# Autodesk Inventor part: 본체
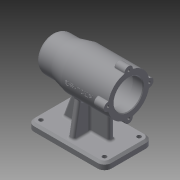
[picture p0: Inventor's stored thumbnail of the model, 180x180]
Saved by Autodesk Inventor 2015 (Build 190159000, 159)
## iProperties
Created: 2019-07
Part Number: 본체
Material: 일반
Document SubType Name: Modeling
Designer: now060
Density: 1 g/cm^3
Appearance: 기본값
Author: now060
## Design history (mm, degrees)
sketch "스케치1"
  geometry: L1 (-56, -35)-(56, -35); L2 (56, -35)-(56, 35); L3 (56, 35)-(-56, 35); L4 (-56, 35)-(-56, -35); L5 (-56, -35)-(56, 35); L6 (56, -35)-(-56, 35); 1 further point
  constraints: 12 end point, 2 midpoint, 2 parallel, 1 horizontal, 1 perpendicular
  dimensions: "d0" = 112 distance of L2.end L3.end; "d1" = 70 distance of L1.end L2.end
extrude "돌출1" new body sketch "스케치1" distance "d2" = 10; taper "d3" = 0 deg
sketch "스케치2"
  geometry: L1 (56, -35)-(56, 35) reference; L2 (-56, 35)-(-56, -35) reference; L3 (-36, 4)-(31, 4); L4 (31, 4)-(31, -4); L5 (31, -4)-(-36, -4); L6 (-36, -4)-(-36, 4); 1 further point
  constraints: 8 end point, 2 parallel, 1 horizontal, 1 perpendicular
  dimensions: "d4" = 25 distance between parallel lines of L1 L4; "d5" = 20 distance between parallel lines of L6 L2; "d6" = 4 distance from line of L3 point (0, 0); "d7" = 8 distance between parallel lines of L5 L3
extrude "돌출2" join sketch "스케치2" distance "d8" = 70; taper "d9" = 0 deg
sketch "스케치3"
  geometry: L1 (56, 35)-(-56, 35) reference; L2 (4, -28)-(-4, -28); L3 (-4, -28)-(-4, 28); L4 (-4, 28)-(4, 28); L5 (4, 28)-(4, -28); L6 (4, -28)-(-4, 28); L7 (-4, -28)-(4, 28); 1 further point
  constraints: 12 end point, 2 midpoint, 2 parallel, 1 horizontal, 1 perpendicular
  dimensions: "d10" = 8 distance between parallel lines of L5 L3; "d11" = 7 distance between parallel lines of L1 L4
extrude "돌출3" join sketch "스케치3" distance "d12" = 70; taper "d13" = 0 deg
feature "면 기울기1" dims angle "d14" = 10 deg
feature "면 기울기2" dims angle "d15" = 20 deg
sketch "스케치4"
  geometry: L1 (-56, 0)-(-56, 10) reference; L2 (-56, 10)-(-31, 10) reference; L3 (-31, 10)-(-31, 80) reference; L4 (-31, 80)-(10.522, 80) reference; L5 (10.522, 80)-(36, 10) reference; L6 (36, 10)-(56, 10) reference; L7 (56, 10)-(56, 0) reference; L8 (56, 0)-(-56, 0) reference; L9 (56, 80)-(-56, 80); L10 (-56, 80)-(-56, 110); L11 (-56, 110)-(11, 110); L12 (11, 110)-(31, 105); L13 (31, 105)-(56, 105); L14 (56, 105)-(56, 80); 1 further point
  constraints: 12 end point, 3 perpendicular, 1 collinear, 1 horizontal, 1 parallel
  dimensions: "d16" = 25 distance of L13.end L9.start; "d17" = 30 vertical distance of L9.start L11.end; "d18" = 25 distance from line of L12.end L14; "d19" = 45 distance from line of L11.end L14; "d20" = 112 distance between parallel lines of L10 L14; "d21" = 0 distance between parallel lines of L1 L10
revolve "회전1" sketch "스케치4" stored, may be unused: angle "d22" = 90 deg
fillet "모깎기1" dims "d23" = 10
sketch "스케치5"
  geometry: C1 r 6 at (-30, 0); 2 further points
  constraints: 2 horizontal alignment, 1 centre point, 1 other
  dimensions: "d24" = 6 radius of C1
extrude "돌출4" join sketch "스케치5" distance "d25" = 16; taper "d26" = 0 deg
sketch "스케치6"
  geometry: A1 r 6 centre (60, 0) between (59.4, -5.97) and (59.4, 5.97) reference; A2 r 6 centre (30, 30) between (35.97, 29.4) and (24.03, 29.4) reference; A3 r 6 centre (0, 0) between (0.6, 5.97) and (0.6, -5.97) reference; A4 r 6 centre (30, -30) between (24.03, -29.4) and (35.97, -29.4) reference; 1 further point
hole "구멍1" sketch "스케치6" at (0, 0), (30, -30), (60, 0), (30, 30) diameter "d30" = 3.242; stored, may be unused: countersink angle "d34" = 90 deg, drill point angle "d36" = 118 deg; dims "d31" = 8, "d32" = 4, "d33" = 2, "d35" = 11
sketch "스케치7"
  geometry: A1 r 30 centre (30, 0) between (35.97, -29.4) and (59.4, -5.97) reference; 1 further point
hole "구멍2" sketch "스케치7" at (30, 0) diameter "d37" = 42; stored, may be unused: countersink angle "d41" = 90 deg, drill point angle "d43" = 0 deg; dims "d38" = 8, "d39" = 4, "d40" = 2, "d42" = 15
sketch "스케치8"
  geometry: C1 r 21 at (0, 0) reference; 1 further point
hole "구멍3" sketch "스케치8" at (0, 0) diameter "d44" = 48; stored, may be unused: countersink angle "d48" = 90 deg, drill point angle "d50" = 0 deg; dims "d45" = 8, "d46" = 4, "d47" = 2, "d49" = 54
sketch "스케치9"
  geometry: C1 r 24 at (0, 0) reference; 1 further point
hole "구멍4" sketch "스케치9" at (0, 0) diameter "d51" = 42; stored, may be unused: countersink angle "d55" = 90 deg, drill point angle "d57" = 0 deg; dims "d52" = 8, "d53" = 4, "d54" = 2, "d56" = 12
sketch "스케치10"
  geometry: C1 r 21 at (0, 0) reference; 1 further point
hole "구멍5" sketch "스케치10" at (0, 0) diameter "d58" = 35; stored, may be unused: countersink angle "d62" = 90 deg, drill point angle "d64" = 0 deg; dims "d59" = 8, "d60" = 4, "d61" = 2, "d63" = 18
sketch "스케치11"
  geometry: C1 r 17.5 at (0, 0) reference; 1 further point
hole "구멍6" sketch "스케치11" at (0, 0) diameter "d65" = 32; stored, may be unused: countersink angle "d69" = 90 deg, drill point angle "d71" = 0 deg; dims "d66" = 8, "d67" = 4, "d68" = 2, "d70" = 4
sketch "스케치12"
  geometry: C1 r 16 at (0, 0) reference; 1 further point
hole "구멍7" sketch "스케치12" at (0, 0) diameter "d72" = 21; stored, may be unused: countersink angle "d76" = 90 deg, drill point angle "d78" = 0 deg; dims "d73" = 8, "d74" = 4, "d75" = 2, "d77" = 3
fillet "모깎기2" dims "d79" = 3
fillet "모깎기3" dims "d80" = 0.3
fillet "모깎기4" dims "d81" = 3
chamfer "모따기1" distance "d82" = 1; stored, may be unused: second distance "d83" = 2, angle "d84" = 45 deg
fillet "모깎기5" dims "d85" = 3
fillet "모깎기6" dims "d86" = 1
fillet "모깎기7" dims "d87" = 10
fillet "모깎기8" dims "d88" = 3
fillet "모깎기9" dims "d89" = 3
fillet "모깎기10" dims "d90" = 3
chamfer "모따기2" distance "d91" = 3; stored, may be unused: second distance "d92" = 2, angle "d93" = 45 deg
sketch "스케치13"
  geometry: A1 r 7 centre (46, -25) between (46, -32) and (53, -25) reference; A2 r 7 centre (46, 25) between (53, 25) and (46, 32) reference; A3 r 7 centre (-46, 25) between (-46, 32) and (-53, 25) reference; A4 r 7 centre (-46, -25) between (-53, -25) and (-46, -32) reference; 1 further point
hole "구멍8" sketch "스케치13" at (-46, -25), (46, -25), (46, 25), (-46, 25) diameter "d94" = 6; stored, may be unused: countersink angle "d98" = 90 deg, drill point angle "d100" = 0 deg; dims "d95" = 8, "d96" = 4, "d97" = 2, "d99" = 3
node "작업 평면1"
sketch "스케치14"
  geometry: L1 (56, 109.226)-(56, 86.771) reference; L2 (56, 85.998)-(56, 74.002) reference; L3 (56, 81.621)-(56, 78.379) reference; 3 further points
  constraints: 1 horizontal alignment, 1 midpoint, 1 other
  dimensions: "d102" = 42 distance from line of L1 point (14, 80)
feature "엠보싱1" sketch "스케치14" dims "d5" = 20, "d103" = 0.5, "d104" = 0
node "솔리드1"
pattern_circular "원형 패턴1" dims angle "d28" = 360 deg
node "절단 모서리 투영1"
